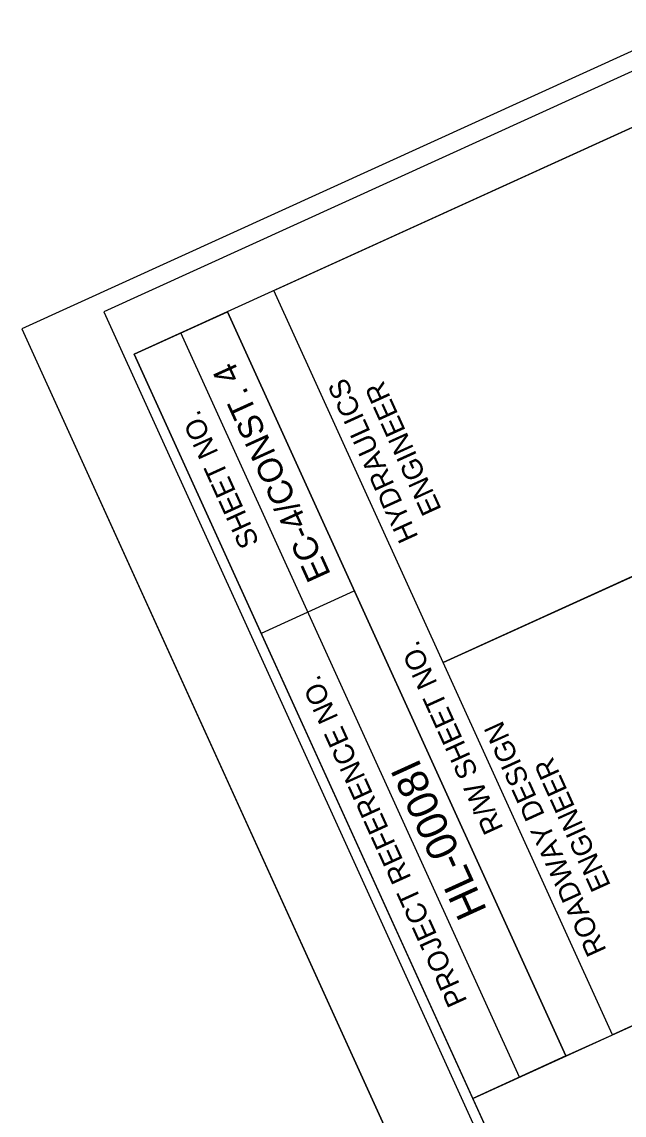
# Model space of a CAD drawing. Extents: x 2097293 to 2098987, y 683915 to 685901.
# Drawn here: x 2097292.8 to 2097440.2, y 685255 to 685522.5 of the extents above; entities that cross this region are included whole.
import ezdxf

# ---------------------------------------------------------------- set-up
doc = ezdxf.new("R2010")
doc.units = 0
for name, color, linetype in [('Sheet Cutting Line CELL', 7, 'Continuous'), ('Sheet Data Field CELL', 7, 'Continuous'), ('Sheet Layout Plan Border', 7, 'Continuous'), ('Sheet Plan CELL', 7, 'Continuous'), ('Sheet Plot Border Inside CELL', 7, 'Continuous'), ('Sheet Plot Border Outside CELL', 7, 'Continuous')]:
    doc.layers.add(name, color=color, linetype=linetype)

msp = doc.modelspace()

# ---------------------------------------------------------------- linework, layer by layer
at = {"layer": 'Sheet Cutting Line CELL'}
msp.add_line((2097292.78, 685447.36), (2097990.05, 683915.04), dxfattribs=at)
at = {"layer": 'Sheet Layout Plan Border'}
for points in [[(2098897.26, 684510.8), (2097941.56, 684075.89), (2097486.05, 685076.91), (2097476.37, 685098.19), (2097403.15, 685259.11), (2097618.23, 685357), (2097567.61, 685468.23), (2098309.25, 685803.01)], [(2098897.26, 684510.8), (2097941.56, 684075.89), (2097486.05, 685076.91), (2097476.38, 685098.16), (2097403.15, 685259.11), (2097618.23, 685357), (2097567.61, 685468.23), (2098309.25, 685803.01)]]:
    msp.add_lwpolyline(points, close=True, dxfattribs=at)
at = {"layer": 'Sheet Plan CELL'}
for p, q in [((2097425.97, 685269.5), (2097343.1, 685451.56)), ((2097425.97, 685269.5), (2097343.1, 685451.56)), ((2097414.56, 685264.29), (2097331.72, 685446.38)), ((2097395.9, 685365.73), (2097498.26, 685412.32)), ((2097351.43, 685372.92), (2097374.16, 685383.32)), ((2097425.97, 685269.5), (2097437.34, 685274.67))]:
    msp.add_line(p, q, dxfattribs=at)
for points in [[(2097320.28, 685441.22), (2097941.56, 684075.89), (2098897.27, 684510.77), (2098276, 685876.08)], [(2098897.27, 684510.77), (2097941.59, 684075.88), (2097403.14, 685259.11), (2097539.72, 685321.27), (2097456.88, 685503.35), (2098276, 685876.08)], [(2097395.9, 685365.73), (2097354.48, 685456.74), (2097456.88, 685503.35), (2097498.31, 685412.33)], [(2097403.14, 685259.11), (2097320.28, 685441.22), (2097343.1, 685451.56), (2097425.97, 685269.5)], [(2097437.34, 685274.67), (2097395.9, 685365.73), (2097498.31, 685412.33), (2097539.72, 685321.27)]]:
    msp.add_lwpolyline(points, close=True, dxfattribs=at)
at = {"layer": 'Sheet Plot Border Inside CELL'}
msp.add_lwpolyline([(2098963.13, 684372.11), (2098273.1, 685888.48), (2097312.85, 685451.54), (2098002.87, 683935.16)], close=True, dxfattribs=at)
at = {"layer": 'Sheet Plot Border Outside CELL'}
msp.add_lwpolyline([(2098986.71, 684368.56), (2098289.45, 685900.88), (2097292.78, 685447.36), (2097990.05, 683915.04)], close=True, dxfattribs=at)

# ---------------------------------------------------------------- texts
at = {"layer": 'Sheet Data Field CELL'}
for s, height, p in [('EC-4/CONST. 4', 6, (2097368.5, 685387.28)), ('HL-0008I', 7.5, (2097406.74, 685305.09))]:
    msp.add_text(s, height=height, rotation=114.4674, dxfattribs=at).set_placement(p)
at = {"layer": 'Sheet Plan CELL'}
for s, height, p in [('HYDRAULICS', 5, (2097389.9, 685396.47)), ('ENGINEER', 5, (2097395.59, 685403.2)), ('SHEET NO.', 5, (2097350.97, 685395.08)), ('R/W SHEET NO.', 5.0001, (2097410.73, 685325.18)), ('PROJECT REFERENCE NO.', 5.0001, (2097401.88, 685282.93)), ('ROADWAY DESIGN', 5.0001, (2097435.96, 685295.33)), ('ENGINEER', 5, (2097437.02, 685311.18))]:
    msp.add_text(s, height=height, rotation=114.4674, dxfattribs=at).set_placement(p)

doc.saveas('drawing.dxf')
